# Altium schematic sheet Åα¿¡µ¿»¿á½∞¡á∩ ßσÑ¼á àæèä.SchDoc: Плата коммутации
size 420 x 297 mm; CompanyName: Университет ИТМО; SheetNumber: 1; SheetTotal: 1; PageSetup: Record=PageOptions¦CenterHorizontal=True¦CenterVertical=True¦PrintScale=0.94¦XCorrection=1.00¦YCorrection=1.00¦PrintKind=1¦BorderSize=5000000¦LeftOffset=0¦BottomOffset=0¦Orientation=1¦PaperLength=1000¦PaperWidth=1000¦Scale=100¦PaperSource=7¦PrintQuality=-4¦MediaType=1¦DitherType=10¦PaperKind=A4¦PrintScaleMode=1; DecimalNumber: XXXX.758756.001; Name1: Плата коммутации
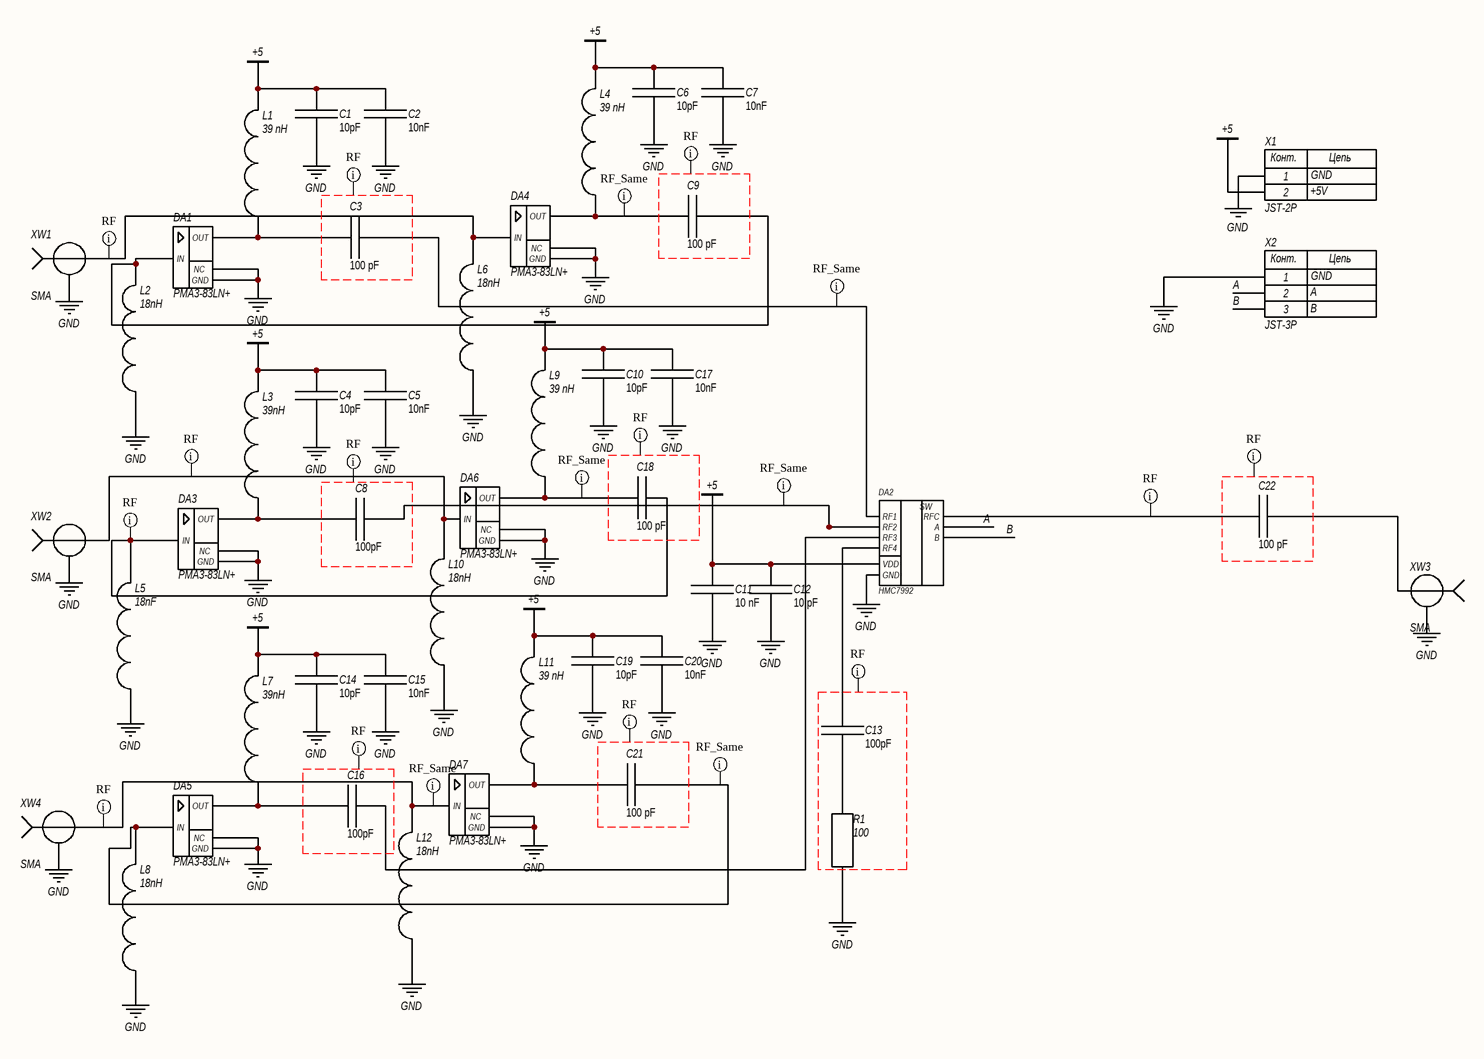
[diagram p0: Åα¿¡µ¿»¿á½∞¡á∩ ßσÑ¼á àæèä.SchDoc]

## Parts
C1  10pF  [FP-GJM155-0_05-IPC_A]
C2  10nF  [FP-GJM155-0_05-IPC_A]
C3  100 pF  [FP-GJM155-0_05-IPC_A]
C4  10pF  [FP-GJM155-0_05-IPC_A]
C5  10nF  [FP-GJM155-0_05-IPC_A]
C6  10pF  [FP-GJM155-0_05-IPC_A]
C7  10nF  [FP-GJM155-0_05-IPC_A]
C8  100pF  [FP-GJM155-0_05-IPC_A]
C9  100 pF  [FP-GJM155-0_05-IPC_A]
C10  10pF  [FP-GJM155-0_05-IPC_A]
C11  10 nF  [FP-GJM155-0_05-IPC_A]
C12  10 pF  [FP-GJM155-0_05-IPC_A]
C13  100pF  [FP-GJM155-0_05-IPC_A]
C14  10pF  [FP-GJM155-0_05-IPC_A]
C15  10nF  [FP-GJM155-0_05-IPC_A]
C16  100pF  [FP-GJM155-0_05-IPC_A]
C17  10nF  [FP-GJM155-0_05-IPC_A]
C18  100 pF  [FP-GJM155-0_05-IPC_A]
C19  10pF  [FP-GJM155-0_05-IPC_A]
C20  10nF  [FP-GJM155-0_05-IPC_A]
C21  100 pF  [FP-GJM155-0_05-IPC_A]
C22  100 pF  [FP-GJM155-0_05-IPC_A]
DA1  PMA3-83LN+  [FP-DQ1225-IPC_A]
DA2  HMC7992  [FP-CP-16-38-IPC_A]
DA3  PMA3-83LN+  [FP-DQ1225-IPC_A]
DA4  PMA3-83LN+  [FP-DQ1225-IPC_A]
DA5  PMA3-83LN+  [FP-DQ1225-IPC_A]
DA6  PMA3-83LN+  [FP-DQ1225-IPC_A]
DA7  PMA3-83LN+  [FP-DQ1225-IPC_A]
L1  39 nH  [FP-0402HP-MFG]
L2  18nH  [FP-0402HP-MFG]
L3  39nH  [FP-0402HP-MFG]
L4  39 nH  [FP-0402HP-MFG]
L5  18nF  [FP-0402HP-MFG]
L6  18nH  [FP-0402HP-MFG]
L7  39nH  [FP-0402HP-MFG]
L8  18nH  [FP-0402HP-MFG]
L9  39 nH  [FP-0402HP-MFG]
L10  18nH  [FP-0402HP-MFG]
L11  39 nH  [FP-0402HP-MFG]
L12  18nH  [FP-0402HP-MFG]
R1  100  [FP-CR0402-IPC_A]
X1  JST-2P  [FP-S2B-XH-A-1_LF_SN-MFG]
X2  JST-3P  [FP-S3B-XH-A-1_LF_SN-MFG]
XW1  SMA  [S-P2152-19CQA]
XW2  SMA  [S-P2152-19CQA]
XW3  SMA  [S-P2152-19CQA]
XW4  SMA  [S-P2152-19CQA]

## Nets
+5: C1.1 C2.1 C4.1 C5.1 C6.1 C7.1 C10.1 C11.2 C12.2 C14.1 C15.1 C17.1 C19.1 C20.1 DA2.6(VDD) L1.2 L3.2 L4.2 L7.2 L9.2 L11.2 X1.2
GND: C1.2 C2.2 C4.2 C5.2 C6.2 C7.2 C10.2 C11.1 C12.1 C14.2 C15.2 C17.2 C19.2 C20.2 DA1.1,3,4,5,6,7,9,10(NC) DA1.13(GND) DA2.2,_3,_5,_10,_11,_13,_14,_16,_17(GND) DA3.1,3,4,5,6,7,9,10(NC) DA3.13(GND) DA4.1,3,4,5,6,7,9,10(NC) DA4.13(GND) DA5.1,3,4,5,6,7,9,10(NC) DA5.13(GND) DA6.1,3,4,5,6,7,9,10(NC) DA6.13(GND) DA7.1,3,4,5,6,7,9,10(NC) DA7.13(GND) L2.1 L5.1 L6.1 L8.1 L10.1 L12.1 R1.1 X1.1 X2.1 XW1.2 XW2.2 XW3.2 XW4.2
A: DA2.8(A) X2.2
B: DA2.7(B) X2.3
NetC3_1: C3.1 DA2.12(RF1)
NetC3_2: C3.2 DA1.8(OUT) L1.1
NetC8_1: C8.1 DA2.9(RF2)
NetC8_2: C8.2 DA3.8(OUT) L3.1
NetC9_1: C9.1 DA1.2(IN) L2.2
NetC9_2: C9.2 DA4.8(OUT) L4.1
NetC13_1: C13.1 R1.2
NetC13_2: C13.2 DA2.1(RF4)
NetC16_1: C16.1 DA2.4(RF3)
NetC16_2: C16.2 DA5.8(OUT) L7.1
NetC18_1: C18.1 DA3.2(IN) L5.2
NetC18_2: C18.2 DA6.8(OUT) L9.1
NetC21_1: C21.1 DA5.2(IN) L8.2
NetC21_2: C21.2 DA7.8(OUT) L11.1
NetC22_1: C22.1 XW3.1
NetC22_2: C22.2 DA2.15(RFC)
NetDA4_2: DA4.2(IN) L6.2 XW1.1
NetDA6_2: DA6.2(IN) L10.2 XW2.1
NetDA7_2: DA7.2(IN) L12.2 XW4.1

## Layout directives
net class RF: (no net found under the mark), NetC18_1, NetC22_2, NetDA4_2, NetDA6_2, NetDA7_2
net class RF_SAME: NetC3_1, NetC8_1, NetC9_2, NetC18_2, NetC21_1, NetDA7_2

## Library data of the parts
C1-C22 = C
L1-L12 = L
R1 = R
X1 = JST-2P: JST type connector; Net1: GND; Net2: +5V
X2 = JST-3P: JST type connector; Net1: GND; Net2: A; Net3: B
